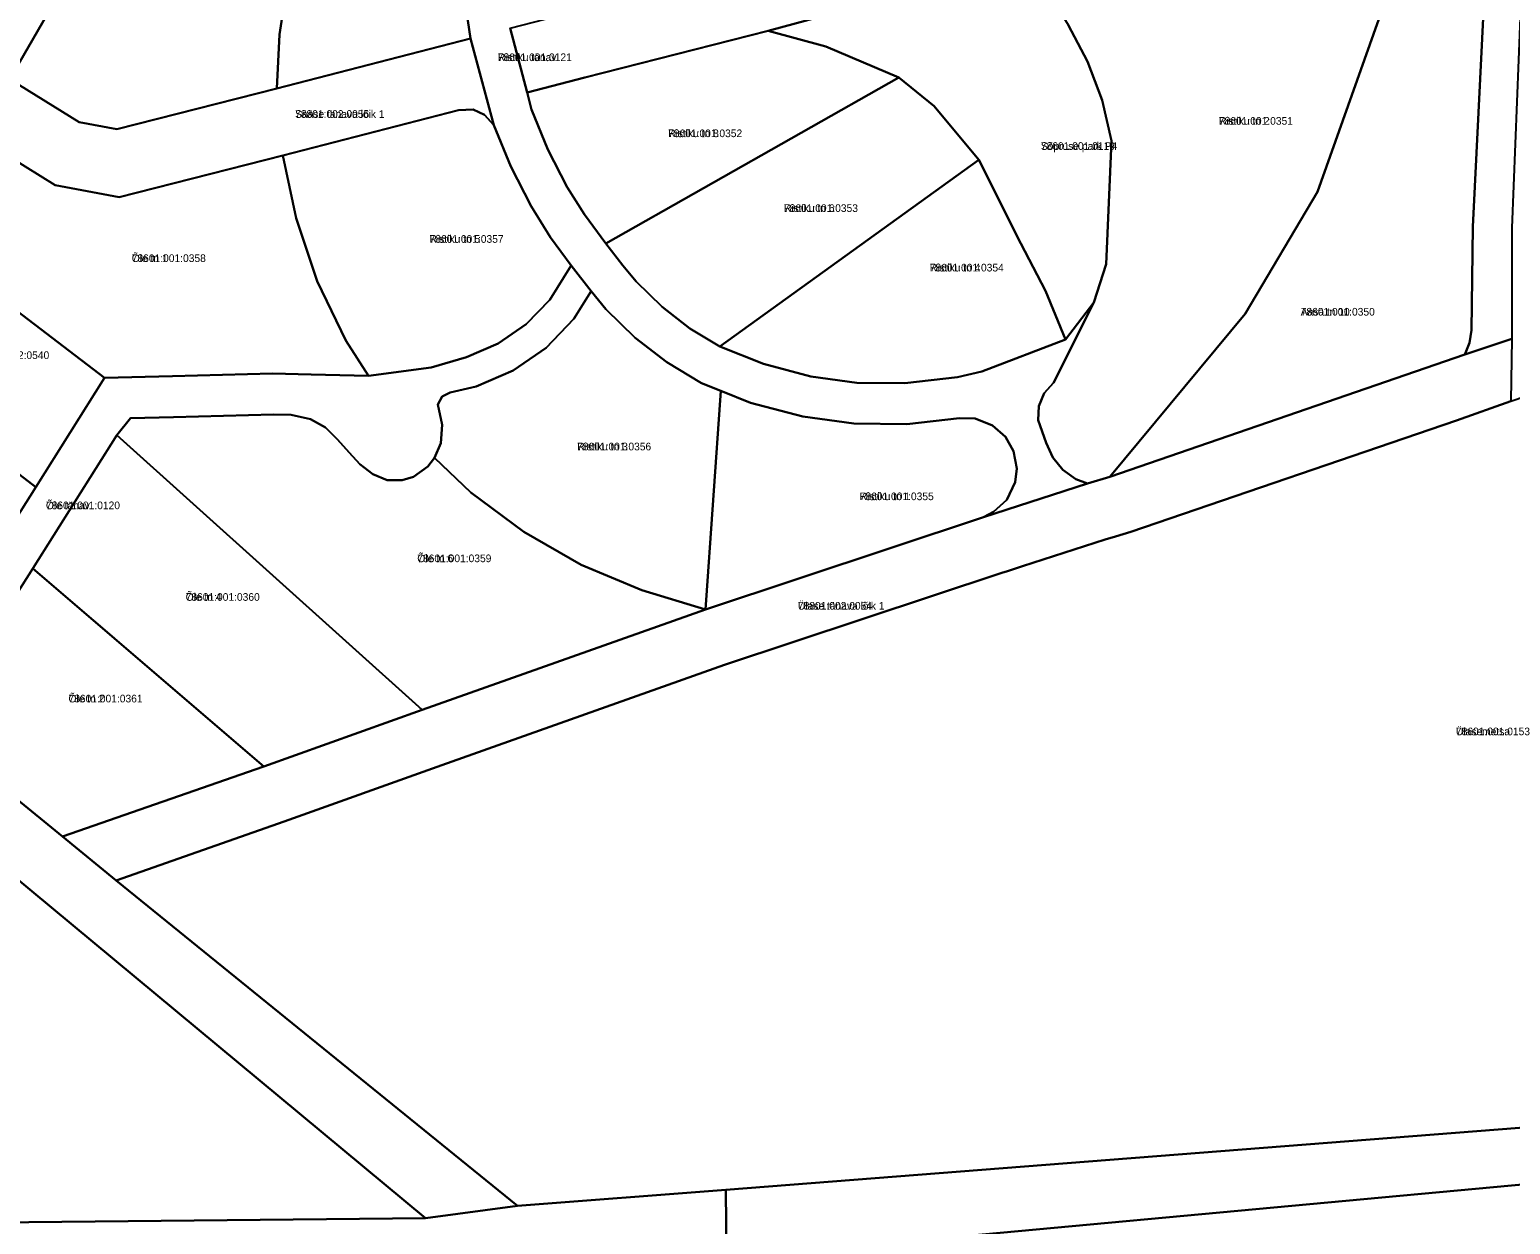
# Model space of a CAD drawing. Extents: x 587616 to 632239, y 6547421 to 6574977.
# Drawn here: x 621332.9 to 621622.8, y 6559618.2 to 6559852.1 of the extents above; entities that cross this region are included whole.
import ezdxf

# ---------------------------------------------------------------- set-up
doc = ezdxf.new("R2010")
doc.units = 0
for name, color, linetype in [('L_AADRESS', 7, 'Continuous'), ('PIIR', 7, 'Continuous'), ('TUNNUS', 7, 'Continuous')]:
    doc.layers.add(name, color=color, linetype=linetype)

msp = doc.modelspace()

# ---------------------------------------------------------------- linework, layer by layer
at = {"layer": 'PIIR'}
for points in [[(621536.44, 6560099.15), (621540.2, 6560106.23), (621559.61, 6560089.04), (621633.19, 6560023.8), (621630.45, 6559908.6), (621626.31, 6559895.58), (621623.07, 6559813.27), (621623.06, 6559791.54), (621613.88, 6559788.46), (621614.76, 6559790.78), (621615.13, 6559793.22), (621615.42, 6559813.44), (621619.1, 6559887.24), (621622.52, 6559911.82), (621622.89, 6559927.25), (621625.01, 6560016.97), (621624.82, 6560018.4), (621624.34, 6560019.9), (621623.31, 6560021.7), (621621.48, 6560023.54), (621559.14, 6560078.76)], [(621259.58, 6559758.94), (621287.55, 6559800.32), (621311.92, 6559839.64), (621319.72, 6559848.57), (621340.1, 6559884.83), (621359.14, 6559917.91), (621369.13, 6559932.82), (621376.95, 6559925.81), (621371.15, 6559915.5), (621349.26, 6559877.47), (621329.06, 6559842.38), (621319.31, 6559827.3), (621309.9, 6559812.66), (621296.45, 6559791.82), (621270.07, 6559749.48)], [(621381.35, 6559840.54), (621381.82, 6559851.12), (621383.22, 6559860.07), (621384.54, 6559866.75), (621389.24, 6559882.8), (621395.01, 6559896.15), (621402.23, 6559908.78), (621408.11, 6559916.77), (621417.64, 6559920.59), (621429.59, 6559926.28), (621438.1, 6559929.8), (621445.45, 6559932.48), (621442.3, 6559928.77), (621440.23, 6559926.29), (621437.26, 6559922.88), (621434.11, 6559919.3), (621431.98, 6559916.3), (621429.12, 6559912.07), (621422.96, 6559899.75), (621419.38, 6559887.02), (621417.92, 6559877.53), (621417.51, 6559867.72), (621418, 6559858.73), (621419.21, 6559850.34)], [(621430.34, 6559839.77), (621427.01, 6559852.33), (621438.4, 6559855.27), (621468.35, 6559862.79), (621541.32, 6559882.59), (621551.32, 6559885.6), (621573.48, 6559892.9), (621605.37, 6559902.99), (621617.69, 6559907.06), (621620.61, 6559909.96), (621622.52, 6559911.82), (621619.1, 6559887.24), (621617.76, 6559890.09), (621616.98, 6559891.77), (621616.1, 6559892.85), (621603.02, 6559888.57), (621577.47, 6559880.52), (621555.06, 6559873.15), (621544.71, 6559870.04), (621528.41, 6559865.64), (621477.5, 6559851.81), (621441.61, 6559842.67)], [(621544.36, 6559764.54), (621570.85, 6559796.43), (621585.02, 6559820.33), (621597.74, 6559856.12), (621603.02, 6559888.57), (621616.1, 6559892.85), (621616.98, 6559891.77), (621617.76, 6559890.09), (621619.1, 6559887.24), (621615.42, 6559813.44), (621615.13, 6559793.22), (621614.76, 6559790.78), (621613.88, 6559788.46)], [(621349.26, 6559877.47), (621384.54, 6559866.75), (621383.22, 6559860.07), (621381.82, 6559851.12), (621381.35, 6559840.54), (621350.01, 6559832.57), (621342.62, 6559833.94), (621329.06, 6559842.38)], [(621528.41, 6559865.64), (621536.2, 6559853.02), (621540.02, 6559845.86), (621542.86, 6559838.25), (621544.67, 6559830.33), (621543.64, 6559806.13), (621541.25, 6559798.65), (621535.67, 6559791.41), (621531.8, 6559800.95), (621526.95, 6559810.19), (621518.75, 6559826.61), (621510, 6559837.08), (621503.05, 6559842.72), (621488.75, 6559848.79), (621477.5, 6559851.81)], [(621477.5, 6559851.81), (621488.75, 6559848.79), (621503.05, 6559842.72), (621445.73, 6559810.23), (621441.54, 6559815.88), (621438.18, 6559821.24), (621434.39, 6559828.62), (621431.2, 6559836.4), (621430.34, 6559839.77), (621441.61, 6559842.67)], [(621319.31, 6559827.3), (621329.06, 6559842.38), (621342.62, 6559833.94), (621350.01, 6559832.57), (621381.35, 6559840.54), (621419.21, 6559850.34), (621423.8, 6559833.36), (621421.99, 6559835.42), (621419.77, 6559836.41), (621416.89, 6559836.33), (621382.49, 6559827.42), (621350.45, 6559819.27), (621337.91, 6559821.59), (621326.1, 6559828.91), (621323.73, 6559829.28), (621322.15, 6559828.92), (621320.64, 6559828.27)], [(621445.73, 6559810.23), (621503.05, 6559842.72), (621510, 6559837.08), (621518.75, 6559826.61), (621468.04, 6559790.04), (621462.19, 6559793.59), (621456.74, 6559797.8), (621451.63, 6559802.77), (621449.08, 6559805.89)], [(621416.89, 6559836.33), (621419.77, 6559836.41), (621421.99, 6559835.42), (621423.8, 6559833.36), (621427.12, 6559825.27), (621431.09, 6559817.52), (621434.92, 6559811.39), (621438.96, 6559805.87), (621434.74, 6559799.19), (621430.14, 6559794.39), (621424.66, 6559790.61), (621418.48, 6559787.97), (621411.56, 6559785.91), (621399.25, 6559784.27), (621394.83, 6559791.19), (621389.25, 6559802.81), (621385.11, 6559815.16), (621382.49, 6559827.42)], [(621347.62, 6559783.88), (621309.9, 6559812.66), (621319.31, 6559827.3), (621320.64, 6559828.27), (621322.15, 6559828.92), (621323.73, 6559829.28), (621326.1, 6559828.91), (621337.91, 6559821.59), (621350.45, 6559819.27), (621382.49, 6559827.42), (621385.11, 6559815.16), (621389.25, 6559802.81), (621394.83, 6559791.19), (621399.25, 6559784.27), (621388.06, 6559784.56), (621380.49, 6559784.73), (621360.92, 6559784.23)], [(621468.04, 6559790.04), (621518.75, 6559826.61), (621526.95, 6559810.19), (621531.8, 6559800.95), (621535.67, 6559791.41), (621519.31, 6559785.12), (621514.58, 6559784.01), (621504.23, 6559782.85), (621494.87, 6559782.96), (621485.84, 6559784.18), (621476.56, 6559786.62)], [(621751.5, 6559609.5), (621673.74, 6559635.67), (621628.75, 6559637.42), (621469.19, 6559624.98), (621428.42, 6559621.8), (621349.86, 6559685.51), (621382.76, 6559697.07), (621413.61, 6559708.09), (621468.96, 6559727.7), (621523.22, 6559745.72), (621524.35, 6559746.08), (621527.28, 6559747.02), (621543.45, 6559752.26), (621545.51, 6559752.82), (621548.45, 6559753.75), (621612.25, 6559775.53), (621622.84, 6559779.35), (621737.44, 6559818.38), (621751.22, 6559789.27), (621795.75, 6559798.04), (621793.74, 6559695.93), (621746.34, 6559693.45), (621751.52, 6559610.26)], [(621296.45, 6559791.82), (621309.9, 6559812.66), (621347.62, 6559783.88), (621334.14, 6559762.52), (621314.82, 6559777.29)], [(621412.17, 6559768.27), (621413.43, 6559771.12), (621413.68, 6559774.69), (621412.82, 6559778.69), (621413.67, 6559780.25), (621415.23, 6559781.03), (621420.34, 6559782.24), (621427.58, 6559785.33), (621434.05, 6559789.8), (621439.49, 6559795.48), (621442.88, 6559800.84), (621445.72, 6559797.36), (621451.49, 6559791.75), (621457.65, 6559786.98), (621464.45, 6559782.86), (621468.21, 6559781.35), (621465.22, 6559738.57), (621452.77, 6559742.32), (621440.88, 6559747.33), (621429.68, 6559753.74), (621419.33, 6559761.45)], [(621382.76, 6559697.07), (621349.86, 6559685.51), (621339.39, 6559694.13), (621378.77, 6559707.85), (621409.75, 6559718.91), (621465.22, 6559738.57), (621519.64, 6559756.65), (621540.01, 6559763.22), (621544.36, 6559764.54), (621613.88, 6559788.46), (621623.06, 6559791.54), (621622.84, 6559779.35), (621612.25, 6559775.53), (621548.45, 6559753.75), (621545.51, 6559752.82), (621543.45, 6559752.26), (621527.28, 6559747.02), (621524.35, 6559746.08), (621523.22, 6559745.72), (621468.96, 6559727.7), (621413.61, 6559708.09)], [(621465.22, 6559738.57), (621468.21, 6559781.35), (621474.05, 6559779.01), (621484.29, 6559776.32), (621494.29, 6559774.97), (621504.63, 6559774.85), (621514.92, 6559776), (621518.03, 6559775.92), (621521.4, 6559774.58), (621523.95, 6559772.35), (621525.54, 6559769.57), (621526.16, 6559766.19), (621525.84, 6559763.48), (621524.18, 6559760.05), (621521.62, 6559757.66), (621519.64, 6559756.65)], [(621288.81, 6559734.74), (621314.82, 6559777.29), (621334.14, 6559762.52), (621307.39, 6559720.18)], [(621350, 6559772.66), (621352.66, 6559776.01), (621361.13, 6559776.23), (621370.91, 6559776.48), (621380.69, 6559776.73), (621384.1, 6559776.65), (621387.91, 6559775.84), (621390.87, 6559774.16), (621393.15, 6559771.88), (621393.19, 6559771.83), (621395.48, 6559769.27), (621397.6, 6559767.02), (621400.1, 6559765.02), (621402.92, 6559763.89), (621405.86, 6559763.87), (621408.09, 6559764.5), (621410.89, 6559766.54), (621412.17, 6559768.27), (621419.33, 6559761.45), (621429.68, 6559753.74), (621440.88, 6559747.33), (621452.77, 6559742.32), (621465.22, 6559738.57), (621409.75, 6559718.91)], [(621333.54, 6559746.6), (621350, 6559772.66), (621409.75, 6559718.91), (621378.77, 6559707.85)], [(621316.21, 6559719.22), (621333.54, 6559746.6), (621378.77, 6559707.85), (621339.39, 6559694.13), (621319.3, 6559710.5), (621317.88, 6559712.87)], [(621319.8, 6559618.48), (621238.2, 6559625.97), (621236.93, 6559649.67), (621286.31, 6559663.41), (621329.11, 6559686.95), (621410.44, 6559619.39)], [(621469.31, 6559611.61), (621630.03, 6559626.49), (621674.68, 6559625), (621752.64, 6559598.79), (621774.25, 6559434.37), (621485.6, 6559175.1), (621452.72, 6559207.92), (621533.88, 6559421.31), (621445.08, 6559430.2), (621367.09, 6559347.18), (621341.32, 6559400.45), (621344.63, 6559416.02), (621358.11, 6559429.85), (621443.86, 6559495.95), (621459.35, 6559515.26), (621467.35, 6559539.61)]]:
    msp.add_lwpolyline(points, close=True, dxfattribs=at)
for points in [[(621427.01, 6559852.33), (621430.34, 6559839.77), (621431.2, 6559836.4), (621434.39, 6559828.62), (621438.18, 6559821.24), (621441.54, 6559815.88), (621445.73, 6559810.23), (621449.08, 6559805.89), (621451.63, 6559802.77), (621456.74, 6559797.8), (621462.19, 6559793.59), (621468.04, 6559790.04), (621476.56, 6559786.62), (621485.84, 6559784.18), (621494.87, 6559782.96), (621504.23, 6559782.85), (621514.58, 6559784.01), (621519.31, 6559785.12), (621535.67, 6559791.41), (621541.25, 6559798.65), (621533.34, 6559782.91), (621531.5, 6559780.88), (621530.45, 6559778.33), (621530.33, 6559775.6), (621531.9, 6559771.17), (621533.21, 6559768.31), (621535.18, 6559765.91), (621537.7, 6559764.1), (621540.01, 6559763.22), (621519.64, 6559756.65), (621521.62, 6559757.66), (621524.18, 6559760.05), (621525.84, 6559763.48), (621526.16, 6559766.19), (621525.54, 6559769.57), (621523.95, 6559772.35), (621521.4, 6559774.58), (621518.03, 6559775.92), (621514.92, 6559776), (621504.63, 6559774.85), (621494.29, 6559774.97), (621484.29, 6559776.32), (621474.05, 6559779.01), (621468.21, 6559781.35), (621464.45, 6559782.86), (621457.65, 6559786.98), (621451.49, 6559791.75), (621445.72, 6559797.36), (621442.88, 6559800.84), (621438.96, 6559805.87), (621434.92, 6559811.39), (621431.09, 6559817.52), (621427.12, 6559825.27), (621423.8, 6559833.36), (621419.21, 6559850.34), (621418, 6559858.73)], [(621597.74, 6559856.12), (621585.02, 6559820.33), (621570.85, 6559796.43), (621544.36, 6559764.54), (621540.01, 6559763.22), (621537.7, 6559764.1), (621535.18, 6559765.91), (621533.21, 6559768.31), (621531.9, 6559771.17), (621530.32, 6559775.59), (621530.33, 6559775.6), (621530.45, 6559778.33), (621531.5, 6559780.88), (621533.34, 6559782.91), (621541.25, 6559798.65), (621543.64, 6559806.13), (621544.67, 6559830.33), (621542.86, 6559838.25), (621540.02, 6559845.86), (621536.2, 6559853.02)], [(620858.08, 6559839.47), (620893.79, 6559809.73), (620889.44, 6559804.34), (620895.1, 6559799.23), (620904.67, 6559792.68), (620929.59, 6559767.2), (620954.82, 6559738.88), (620980.39, 6559710.57), (620989.2, 6559702.5), (621028.4, 6559660.4), (621045.82, 6559651.66), (621099.7, 6559640.86), (621144.33, 6559629.97), (621147.12, 6559628.13), (621204.28, 6559629.11), (621238.2, 6559625.97), (621319.8, 6559618.48), (621410.44, 6559619.39), (621428.42, 6559621.8), (621469.19, 6559624.98), (621469.31, 6559611.61)], [(621307.39, 6559720.18), (621334.14, 6559762.52), (621347.62, 6559783.88), (621360.92, 6559784.23), (621380.49, 6559784.73), (621388.06, 6559784.56), (621399.25, 6559784.27), (621411.56, 6559785.91), (621418.48, 6559787.97), (621424.66, 6559790.61), (621430.14, 6559794.39), (621434.74, 6559799.19), (621438.96, 6559805.87), (621442.88, 6559800.84), (621439.49, 6559795.48), (621434.05, 6559789.8), (621427.58, 6559785.33), (621420.34, 6559782.24), (621415.23, 6559781.03), (621413.67, 6559780.25), (621412.82, 6559778.69), (621413.68, 6559774.69), (621413.43, 6559771.12), (621412.17, 6559768.27), (621410.89, 6559766.54), (621408.09, 6559764.5), (621405.86, 6559763.87), (621402.92, 6559763.89), (621400.1, 6559765.02), (621397.6, 6559767.02), (621395.48, 6559769.27), (621393.19, 6559771.83), (621390.87, 6559774.16), (621387.91, 6559775.84), (621384.1, 6559776.65), (621380.69, 6559776.73), (621370.91, 6559776.48), (621361.13, 6559776.23), (621352.66, 6559776.01), (621350, 6559772.66), (621333.54, 6559746.6), (621316.21, 6559719.22)], [(621319.3, 6559710.5), (621339.39, 6559694.13), (621349.86, 6559685.51), (621428.42, 6559621.8), (621410.44, 6559619.39), (621329.11, 6559686.95)], [(622188.3, 6559598), (622026.64, 6559591.85), (622008.1, 6559591.8), (621827.9, 6559586.2), (621805.6, 6559586.4), (621783, 6559590), (621758, 6559597.2), (621752.64, 6559598.79), (621674.68, 6559625), (621630.03, 6559626.49), (621469.31, 6559611.61), (621469.19, 6559624.98), (621628.75, 6559637.42), (621673.74, 6559635.67), (621751.5, 6559609.5), (621760.8, 6559606.8), (621785.2, 6559599.8), (621806.4, 6559596.4), (621827.74, 6559596.19), (622008.59, 6559601.8), (622031.61, 6559602.47), (622187.87, 6559607.16)]]:
    msp.add_lwpolyline(points, dxfattribs=at)

# ---------------------------------------------------------------- texts
at = {"layer": 'L_AADRESS'}
for s, p in [('Ristiku tänav', (621424.56, 6559845.91)), ('Sääse tänava lõik 1', (621384.9, 6559834.8)), ('Ristiku tn 2', (621565.71, 6559833.45)), ('Ristiku tn 8', (621457.91, 6559831.02)), ('Sõpruse park P4', (621530.87, 6559828.53)), ('Ristiku tn 6', (621480.57, 6559816.38)), ('Ristiku tn 5', (621411.21, 6559810.34)), ('Õle tn 1', (621352.93, 6559806.58)), ('Ristiku tn 4', (621509.11, 6559804.73)), ('Aasa tn 10', (621581.73, 6559796.09)), ('Ristiku tn 3', (621440.1, 6559769.71)), ('Ristiku tn 1', (621495.4, 6559759.96)), ('Õle tänav', (621336.13, 6559758.19)), ('Õle tn 6', (621408.82, 6559747.82)), ('Õle tn 4', (621363.48, 6559740.26)), ('Ülase tänava lõik 1', (621483.32, 6559738.53)), ('Õle tn 2', (621340.55, 6559720.37)), ('Ülasemetsa', (621612.11, 6559713.94))]:
    msp.add_text(s, height=1.5, dxfattribs=at).set_placement(p)
at = {"layer": 'TUNNUS'}
for s, p in [('78601:001:0121', (621424.56, 6559845.91)), ('78801:002:0056', (621384.9, 6559834.8)), ('78601:001:0351', (621565.71, 6559833.45)), ('78601:001:0352', (621457.91, 6559831.02)), ('78601:001:0119', (621530.87, 6559828.53)), ('78601:001:0353', (621480.57, 6559816.38)), ('78601:001:0357', (621411.21, 6559810.34)), ('78601:001:0358', (621352.93, 6559806.58)), ('78601:001:0354', (621509.11, 6559804.73)), ('78601:001:0350', (621581.73, 6559796.09)), ('78801:002:0540', (621322.28, 6559787.59)), ('78601:001:0356', (621440.1, 6559769.71)), ('78601:001:0355', (621495.4, 6559759.96)), ('78601:001:0120', (621336.13, 6559758.19)), ('78601:001:0359', (621408.82, 6559747.82)), ('78601:001:0360', (621363.48, 6559740.26)), ('78801:002:0054', (621483.32, 6559738.53)), ('78601:001:0361', (621340.55, 6559720.37)), ('78601:001:0153', (621612.11, 6559713.94))]:
    msp.add_text(s, height=1.5, dxfattribs=at).set_placement(p)

doc.saveas('drawing.dxf')
